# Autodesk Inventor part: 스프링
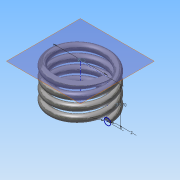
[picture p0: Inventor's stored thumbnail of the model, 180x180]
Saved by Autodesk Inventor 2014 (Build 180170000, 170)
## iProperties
Created: 2015-04
Part Number: 스프링
Material: 강철, 탄소
Document SubType Name: Modeling
Designer: Administrator
Density: 7.87 g/cm^3
Appearance: 반연마
Mass: 4.78743 g
Surface Area: 12.5262 cm^2
Volume: 0.608313 cm^3
Author: Administrator
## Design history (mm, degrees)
sketch "스케치2"
  geometry: L1 (0, 0)-(8, 0); L2 (8, 0)-(8, 11.5); L3 (8, 11.5)-(0, 11.5); L4 (0, 11.5)-(0, 0); C1 r 1 at (8, 0)
  constraints: 8 end point, 2 parallel, 1 centre point, 1 coincident, 1 horizontal, 1 perpendicular
  dimensions: "d0" = 16 diameter of L2 L4; "d1" = 11.50049 distance between parallel lines of L3 L1 (derived); "d2" = 2 diameter of C1
feature "코일1" pitch "d3" = 10; turns "d5" = 4; dims "d4" = 11.50049 (= d1), "d6" = 0, angle "d7" = 90 deg, angle "d8" = 90 deg, "d9" = 0, "d10" = 0
sketch "스케치3"
  geometry: L1 (-9, 0)-(-7, 0) reference; 1 further point
  constraints: 1 horizontal alignment
extrude "돌출1" cut sketch "스케치3" stored distance "d11" = 10; taper "d12" = 0 deg
node "작업 평면1"
sketch "스케치4"
  geometry: L1 (9, 0)-(7, 0) reference; 1 further point
  constraints: 1 horizontal alignment
extrude "돌출2" cut sketch "스케치4" stored distance "d13" = 10; taper "d14" = 0 deg
node "솔리드1"
node "절단 모서리 투영1"
node "절단 모서리 투영2"
